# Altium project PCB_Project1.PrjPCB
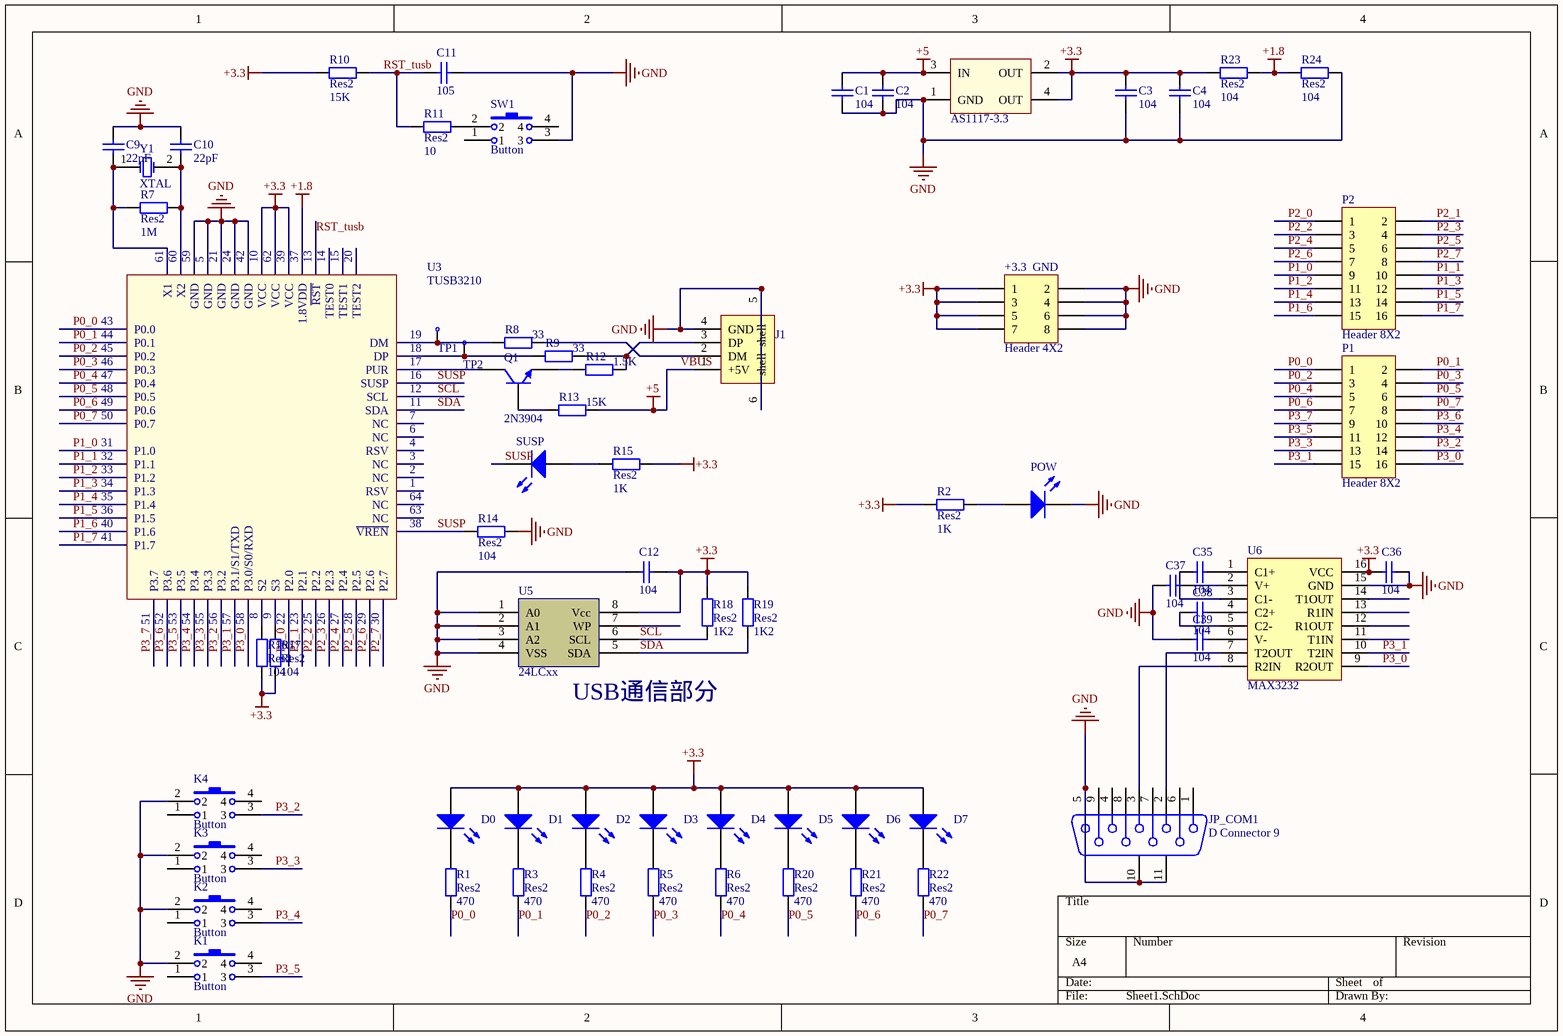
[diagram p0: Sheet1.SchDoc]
1 sheet, 65 parts. Net scope: global (net labels, ports and power ports of the same name join across sheets).
Board file: PCB1.PcbDoc

## Sheet Sheet1.SchDoc
size A4

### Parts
+3.3_GND  Header 4X2  [HDR2X4]
AS1117-3.3  AS1117-3.3  [DSO-G3]  (value not drawn)
C1  value 104  [C0805]  (hidden comment: Cap)
C2  value 104  [C0805]  (hidden comment: Cap)
C3  value 104  [C0805]  (hidden comment: Cap)
C4  value 104  [C0805]  (hidden comment: Cap)
C9  value 22pF  [C0805]  (hidden comment: Cap)
C10  value 22pF  [C0805]  (hidden comment: Cap)
C11  value 105  [C0805]  (hidden comment: Cap)
C12  value 104  [C0805]  (hidden comment: Cap)
C35  value 104  [C0805]  (hidden comment: Cap)
C36  value 104  [C0805]  (hidden comment: Cap)
C37  value 104  [C0805]  (hidden comment: Cap)
C38  value 104  [C0805]  (hidden comment: Cap)
C39  value 104  [C0805]  (hidden comment: Cap)
D0  LED1  [LED]  (value not drawn)
D1  LED1  [LED]  (value not drawn)
D2  LED1  [LED]  (value not drawn)
D3  LED1  [LED]  (value not drawn)
D4  LED1  [LED]  (value not drawn)
D5  LED1  [LED]  (value not drawn)
D6  LED1  [LED]  (value not drawn)
D7  LED1  [LED]  (value not drawn)
J1  USB_A  [USB-A]  (value not drawn)
JP_COM1  D Connector 9  [DSUB1.385-2H9]
K1  Button  [SW-6]
K2  Button  [SW-6]
K3  Button  [SW-6]
K4  Button  [SW-6]
P1  Header 8X2  [HDR2X8]
P2  Header 8X2  [HDR2X8]
POW  LED1  [LED]  (value not drawn)
Q1  2N3904  [TO-92A]
R1  Res2  value 470  [c0805]
R2  Res2  value 1K  [c0805]
R3  Res2  value 470  [c0805]
R4  Res2  value 470  [c0805]
R5  Res2  value 470  [c0805]
R6  Res2  value 470  [c0805]
R7  Res2  value 1M  [c0805]
R8  value 33  [c0805]  (hidden comment: Res2)
R9  value 33  [c0805]  (hidden comment: Res2)
R10  Res2  value 15K  [c0805]
R11  Res2  value 10  [c0805]
R12  value 1.5K  [c0805]  (hidden comment: Res2)
R13  value 15K  [c0805]  (hidden comment: Res2)
R14  Res2  value 104  [c0805]
R15  Res2  value 1K  [c0805]
R16  Res2  value 104  [c0805]
R17  Res2  value 104  [c0805]
R18  Res2  value 1K2  [c0805]
R19  Res2  value 1K2  [c0805]
R20  Res2  value 470  [c0805]
R21  Res2  value 470  [c0805]
R22  Res2  value 470  [c0805]
R23  Res2  value 104  [c0805]
R24  Res2  value 104  [c0805]
SUSP  LED1  [LED]  (value not drawn)
SW1  Button  [SW-6]
TP1  TestPoint  [TESTPOINT]  (value not drawn)
TP2  TestPoint  [TESTPOINT]  (value not drawn)
U3  TUSB3210  [Quad64]
U5  24LCxx  [DIP-8]
U6  MAX3232  [SOP16]
Y1  XTAL  [GJA-M]

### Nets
+1.8: R23.1 R24.2 U3.37(1.8VDD)
+3.3: +3.3_GND.1 +3.3_GND.3 +3.3_GND.5 +3.3_GND.7 AS1117-3.3.2(OUT) AS1117-3.3.4(OUT) C3.2 C4.2 C12.2 C36.1 D0.1(A) D1.1(A) D2.1(A) D3.1(A) D4.1(A) D5.1(A) D6.1(A) D7.1(A) R2.1 R10.2 R15.1 R16.1 R17.1 R18.2 R19.2 R23.2 U3.10(VCC) U3.39(VCC) U3.62(VCC) U5.8(Vcc) U6.16(VCC)
GND: +3.3_GND.2 +3.3_GND.4 +3.3_GND.6 +3.3_GND.8 AS1117-3.3.1(GND) C1.1 C2.1 C3.1 C4.1 C9.2 C10.2 C11.2 C12.1 C36.2 C37.1 C39.1 J1.4(GND) J1.5(shell) J1.6(shell) JP_COM1.5 JP_COM1.10(MH1) JP_COM1.11(MH2) K1.2 K2.2 K3.2 K4.2 POW.2(K) R14.2 R24.1 SW1.3 U3.5(GND) U3.21(GND) U3.24(GND) U3.42(GND) U3.59(GND) U5.1(A0) U5.2(A1) U5.3(A2) U5.4(VSS) U6.15(GND)
VBUS: AS1117-3.3.3(IN) C1.2 C2.2 J1.1(+5V) R13.2  [also labelled +5]
P0_0: P1.1 R1.1 U3.43(P0.0)
P0_1: P1.2 R3.1 U3.44(P0.1)
P0_2: P1.3 R4.1 U3.45(P0.2)
P0_3: P1.4 R5.1 U3.46(P0.3)
P0_4: P1.5 R6.1 U3.47(P0.4)
P0_5: P1.6 R20.1 U3.48(P0.5)
P0_6: P1.7 R21.1 U3.49(P0.6)
P0_7: P1.8 R22.1 U3.50(P0.7)
P1_0: P2.9 U3.31(P1.0)
P1_1: P2.10 U3.32(P1.1)
P1_2: P2.11 U3.33(P1.2)
P1_3: P2.12 U3.34(P1.3)
P1_4: P2.13 U3.35(P1.4)
P1_5: P2.14 U3.36(P1.5)
P1_6: P2.15 U3.40(P1.6)
P1_7: P2.16 U3.41(P1.7)
P2_0: P2.1 U3.22(P2.0)
P2_1: P2.2 U3.23(P2.1)
P2_2: P2.3 U3.25(P2.2)
P2_3: P2.4 U3.26(P2.3)
P2_4: P2.5 U3.27(P2.4)
P2_5: P2.6 U3.28(P2.5)
P2_6: P2.7 U3.29(P2.6)
P2_7: P2.8 U3.30(P2.7)
P3_0: P1.16 U3.58(P3.0/S0/RXD) U6.9(R2OUT)
P3_1: P1.15 U3.57(P3.1/S1/TXD) U6.10(T2IN)
P3_2: K4.3 P1.14 U3.56(P3.2)
P3_3: K3.3 P1.13 U3.55(P3.3)
P3_4: K2.3 P1.12 U3.54(P3.4)
P3_5: K1.3 P1.11 U3.53(P3.5)
P3_6: P1.10 U3.52(P3.6)
P3_7: P1.9 U3.51(P3.7)
RST_tusb: C11.1 R10.1 R11.2 U3.13(~{RST})
SCL: R18.1 U3.12(SCL) U5.6(SCL)
SDA: R19.1 U3.11(SDA) U5.5(SDA)
SUSP: R14.1 SUSP.2(K) U3.16(SUSP) U3.38(~{VREN})
NetC9_1: C9.1 R7.1 U3.61(X1) Y1.1(OSC1)
NetC10_1: C10.1 R7.2 U3.60(X2) Y1.2(OSC2)
NetC35_1: C35.1 U6.1(C1+)
NetC35_2: C35.2 U6.3(C1-)
NetC37_2: C37.2 U6.2(V+)
NetC38_1: C38.1 U6.4(C2+)
NetC38_2: C38.2 U6.5(C2-)
NetC39_2: C39.2 U6.6(V-)
NetD0_2: D0.2(K) R1.2
NetD1_2: D1.2(K) R3.2
NetD2_2: D2.2(K) R4.2
NetD3_2: D3.2(K) R5.2
NetD4_2: D4.2(K) R6.2
NetD5_2: D5.2(K) R20.2
NetD6_2: D6.2(K) R21.2
NetD7_2: D7.2(K) R22.2
NetJ1_2: J1.2(DM) R8.1
NetJ1_3: J1.3(DP) R9.1 R12.2
NetJP_COM1_2: JP_COM1.2 U6.7(T2OUT)
NetJP_COM1_3: JP_COM1.3 U6.8(R2IN)
NetPOW_1: POW.1(A) R2.2
NetQ1_1: Q1.1(E) R12.1
NetQ1_2: Q1.2(B) R13.1
NetQ1_3: Q1.3(C) U3.17(PUR)
NetR8_2: R8.2 TP1.1(TP) U3.19(DM)
NetR9_2: R9.2 TP2.1(TP) U3.18(DP)
NetR11_1: R11.1 SW1.2
NetR15_2: R15.2 SUSP.1(A)
NetR16_2: R16.2 U3.8(S2)
NetR17_2: R17.2 U3.9(S3)

Not connected (* = marked no-connect by the designer): JP_COM1 1 4 6 7 8 9; K1 1 4; K2 1 4; K3 1 4; K4 1 4; SW1 1 4; U3 1(RSV) 2(NC) 3(NC) 4(RSV) 6(NC) 7(NC) 14(TEST0) 15(TEST1) 20(TEST2) 63(NC) 64(NC); U5 7(WP); U6 11(T1IN) 12(R1OUT) 13(R1IN) 14(T1OUT)

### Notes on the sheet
- (near U5) USB通信部分

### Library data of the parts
+3.3_GND = Header 4X2: Header, 4-Pin, Dual row
C1-C4 C9-C12 C35-C39 = Cap: Capacitor
D0-D7 POW SUSP = LED1: Typical RED GaAs LED
JP_COM1 = D Connector 9: Receptacle Assembly, 9 Position, Right Angle; PackageDocument: O; Positions: 9
K1-K4 SW1 = Button_4
P1 P2 = Header 8X2: Header, 8-Pin, Dual row
Q1 = 2N3904: NPN General Purpose Amplifier
R1-R24 = Res2: Resistor
TP1 TP2 = TestPoint: TespPoint
Y1 = XTAL: Crystal Oscillator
